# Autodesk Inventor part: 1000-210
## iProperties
Created: 2007-03
Part Number: 1000-210
Document SubType Name: Modeling
Designer: Andy Moles
Material: ABS Plastic
Mass: 27.7243 g
Surface Area: 118.536 cm^2
Volume: 26.155 cm^3
Density: 1.06 g/cm^3
Author: Andy Moles
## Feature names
1. Base1
2. Hole3
